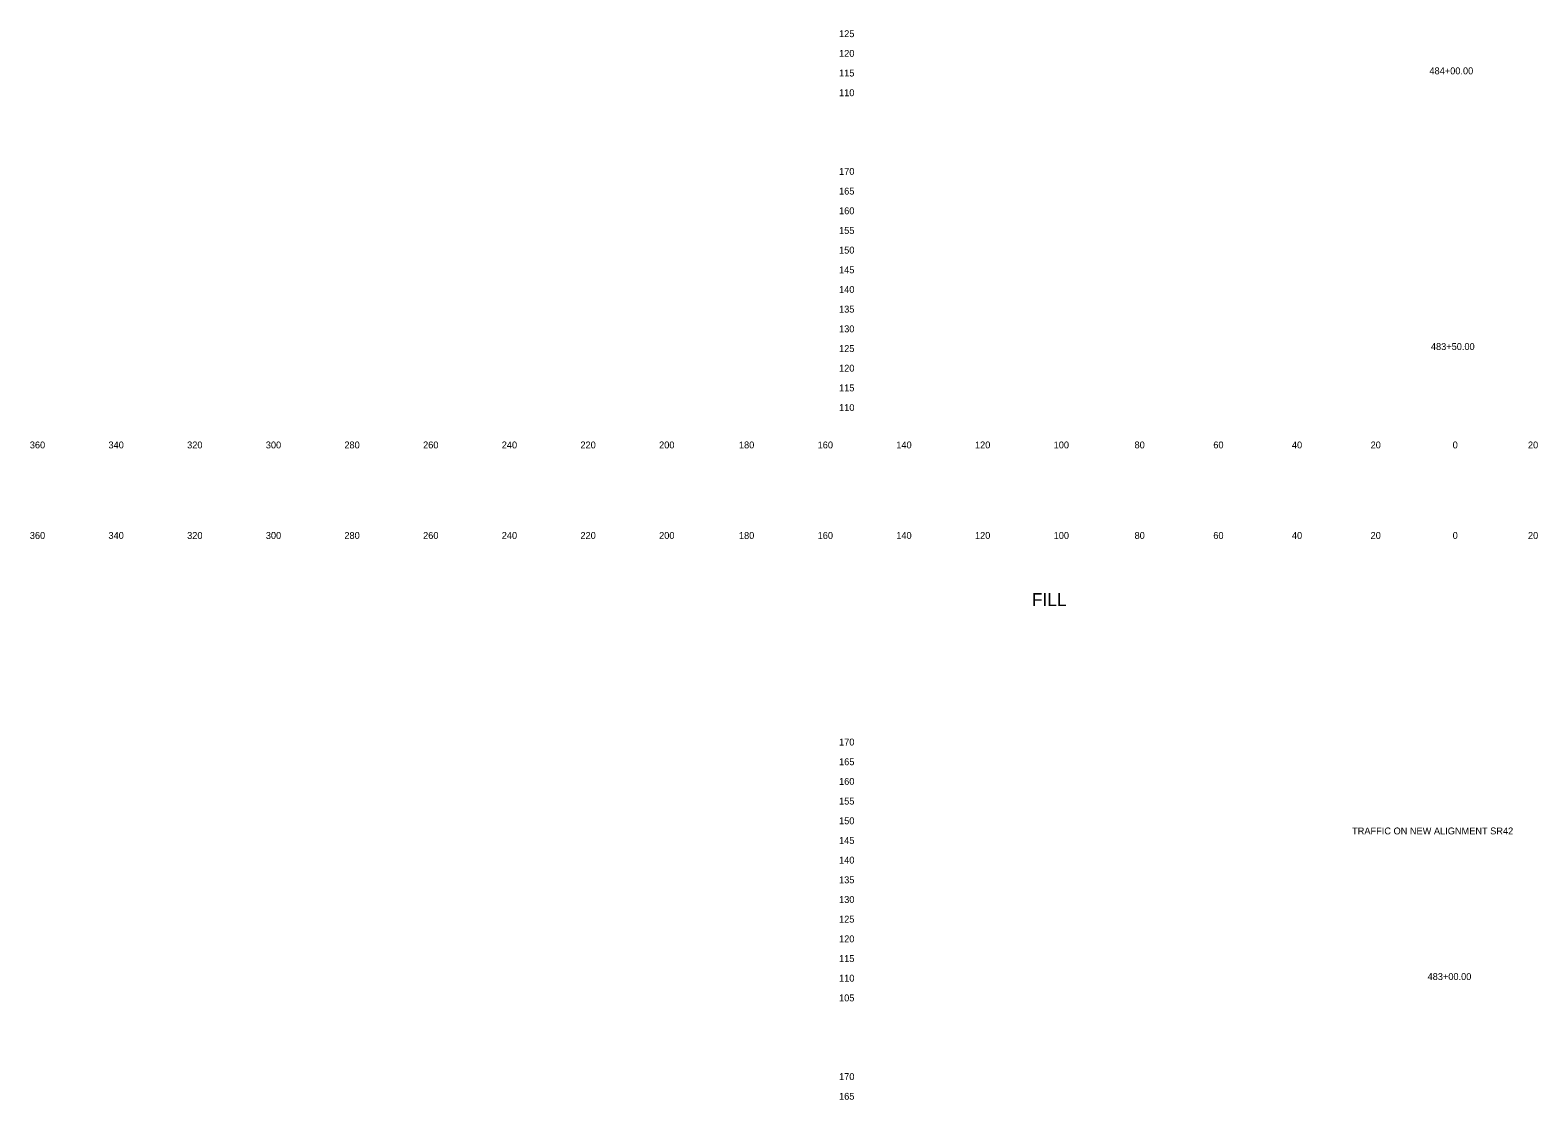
# Model space of a CAD drawing. Extents: x 21281 to 22024, y 6472 to 15208.
# Drawn here: x 21280.5 to 21663.8, y 12749.8 to 13021.6 of the extents above; entities that cross this region are included whole.
import ezdxf

# ---------------------------------------------------------------- set-up
doc = ezdxf.new("R2010")
doc.units = 0
for name, color, linetype in [('XS_SHEET_LABELS_ELEVATION', 7, 'Continuous'), ('XS_SHEET_LABELS_OFFSET', 7, 'Continuous'), ('XS_SHEET_LABELS_STATION', 7, 'Continuous')]:
    doc.layers.add(name, color=color, linetype=linetype)

msp = doc.modelspace()

# ---------------------------------------------------------------- texts
at = {"layer": 'XS_SHEET_LABELS_ELEVATION'}
for s, p in [('  125  ', (21484.84, 13019.84)), ('  120  ', (21484.84, 13014.84)), ('  115  ', (21484.84, 13009.84)), ('  110  ', (21484.84, 13004.84)), ('  170  ', (21484.84, 12984.84)), ('  165  ', (21484.84, 12979.84)), ('  160  ', (21484.84, 12974.84)), ('  155  ', (21484.84, 12969.84)), ('  150  ', (21484.84, 12964.84)), ('  145  ', (21484.84, 12959.84)), ('  140  ', (21484.84, 12954.84)), ('  135  ', (21484.84, 12949.84)), ('  130  ', (21484.84, 12944.84)), ('  125  ', (21484.84, 12939.84)), ('  120  ', (21484.84, 12934.84)), ('  115  ', (21484.84, 12929.84)), ('  110  ', (21484.84, 12924.84)), ('  170  ', (21484.84, 12839.84)), ('  165  ', (21484.84, 12834.84)), ('  160  ', (21484.84, 12829.84)), ('  155  ', (21484.84, 12824.84)), ('  150  ', (21484.84, 12819.84)), ('  145  ', (21484.84, 12814.84)), ('  140  ', (21484.84, 12809.84)), ('  135  ', (21484.84, 12804.84)), ('  130  ', (21484.84, 12799.84)), ('  125  ', (21484.84, 12794.84)), ('  120  ', (21484.84, 12789.84)), ('  115  ', (21484.84, 12784.84)), ('  110  ', (21484.84, 12779.84)), ('  105  ', (21484.84, 12774.84)), ('  170  ', (21484.84, 12754.84)), ('  165  ', (21484.84, 12749.84))]:
    msp.add_text(s, height=1.75, dxfattribs=at).set_placement(p)
at = {"layer": 'XS_SHEET_LABELS_OFFSET'}
for s, height, p in [('  360  ', 1.75, (21279.14, 12915.34)), ('  340  ', 1.75, (21299.13, 12915.34)), ('  320  ', 1.75, (21319.13, 12915.34)), ('  300  ', 1.75, (21339.13, 12915.34)), ('  280  ', 1.75, (21359.1, 12915.34)), ('  260  ', 1.75, (21379.11, 12915.34)), ('  240  ', 1.75, (21399.1, 12915.34)), ('  220  ', 1.75, (21419.1, 12915.34)), ('  200  ', 1.75, (21439.1, 12915.34)), ('  180  ', 1.75, (21459.39, 12915.34)), ('  160  ', 1.75, (21479.4, 12915.34)), ('  140  ', 1.75, (21499.39, 12915.34)), ('  120  ', 1.75, (21519.39, 12915.34)), ('  100  ', 1.75, (21539.39, 12915.34)), ('  80  ', 1.75, (21559.95, 12915.34)), ('  60  ', 1.75, (21579.97, 12915.34)), ('  40  ', 1.75, (21599.95, 12915.34)), ('  20  ', 1.75, (21619.95, 12915.34)), ('  0  ', 1.75, (21640.81, 12915.34)), ('  0  ', 1.75, (21640.81, 12915.34)), ('  20  ', 1.75, (21659.95, 12915.34)), ('  360  ', 1.75, (21279.14, 12892.34)), ('  340  ', 1.75, (21299.13, 12892.34)), ('  320  ', 1.75, (21319.13, 12892.34)), ('  300  ', 1.75, (21339.13, 12892.34)), ('  280  ', 1.75, (21359.1, 12892.34)), ('  260  ', 1.75, (21379.11, 12892.34)), ('  240  ', 1.75, (21399.1, 12892.34)), ('  220  ', 1.75, (21419.1, 12892.34)), ('  200  ', 1.75, (21439.1, 12892.34)), ('  180  ', 1.75, (21459.39, 12892.34)), ('  160  ', 1.75, (21479.4, 12892.34)), ('  140  ', 1.75, (21499.39, 12892.34)), ('  120  ', 1.75, (21519.39, 12892.34)), ('  100  ', 1.75, (21539.39, 12892.34)), ('  80  ', 1.75, (21559.95, 12892.34)), ('  60  ', 1.75, (21579.97, 12892.34)), ('  40  ', 1.75, (21599.95, 12892.34)), ('  20  ', 1.75, (21619.95, 12892.34)), ('  0  ', 1.75, (21640.81, 12892.34)), ('  0  ', 1.75, (21640.81, 12892.34)), ('  20  ', 1.75, (21659.95, 12892.34)), ('FILL', 3.273, (21535.18, 12875.29))]:
    msp.add_text(s, height=height, dxfattribs=at).set_placement(p)
at = {"layer": 'XS_SHEET_LABELS_STATION'}
for s, p in [('  484+00.00  ', (21634.91, 13010.4)), ('  483+50.00  ', (21635.28, 12940.34)), ('TRAFFIC ON NEW ALIGNMENT SR42', (21616.55, 12817.26)), ('  483+00.00  ', (21634.43, 12780.26))]:
    msp.add_text(s, height=1.75, dxfattribs=at).set_placement(p)

doc.saveas('drawing.dxf')
